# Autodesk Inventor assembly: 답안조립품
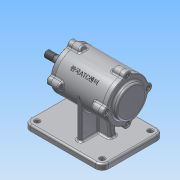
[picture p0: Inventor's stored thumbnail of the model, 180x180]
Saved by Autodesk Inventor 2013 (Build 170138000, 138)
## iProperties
Created: 2015-12
Part Number: 답안조립품
Document SubType Name: Assembly
Designer: Administrator
Author: Administrator
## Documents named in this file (9)
- C:\Users\Administrator\Desktop\451208V1020\답안조립품.iam
- C:\Users\Administrator\Desktop\451208V1020\본체.ipt
- C:\Users\Administrator\Desktop\451208V1020\축.ipt
- C:\Users\Administrator\Desktop\451208V1020\베어링 6204.ipt
- C:\Users\Administrator\Desktop\451208V1020\키(4 x 4 x 12).ipt
- C:\Users\Administrator\Desktop\451208V1020\커버2.ipt
- C:\Users\Administrator\Desktop\451208V1020\볼트 M4 x 12.ipt
- C:\Users\Administrator\Desktop\451208V1020\커버.ipt
- C:\Users\Administrator\Desktop\451208V1020\오일실.ipt
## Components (4 placed, 3 different names)
1. KS B 2023 6204 - 20 x 47 x 14:1
2. KS B 2023 6204 - 20 x 47 x 14:2
3. KS B 1311 (I) 4 x 4 x 12:1 — 각도:1
4. KS B 2804 D D - 20 32 8:1
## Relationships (1: Angle 1)
- 각도:1 [Angle]: KS B 1311 (I) 4 x 4 x 12:1
